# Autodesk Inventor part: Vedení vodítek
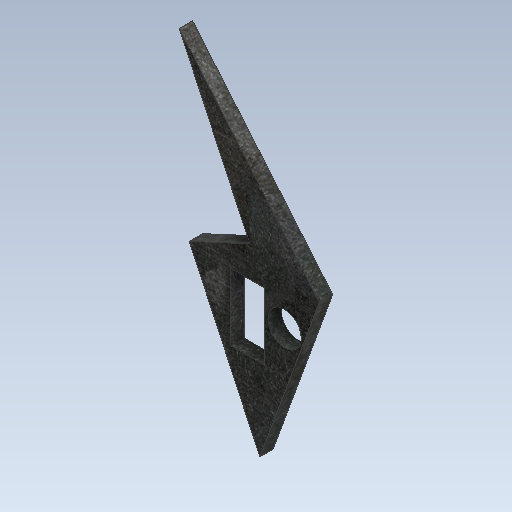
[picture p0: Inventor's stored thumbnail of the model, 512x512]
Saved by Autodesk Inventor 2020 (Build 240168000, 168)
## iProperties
Created: 2025-03
Part Number: Vedení vodítek
Material: Ocel
Document SubType Name: Modeling
Designer: doma
Density: 7.85 g/cm^3
Appearance: Plech
Mass: 300.864 g
Surface Area: 148.491 cm^2
Volume: 38.3267 cm^3
Author: doma
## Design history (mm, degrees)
sketch "Náčrt1"
  geometry: L1 (2141.663, -169.537)-(2099.366, -78.832); L2 (2127.103, -43.665)-(2093.357, 28.704); L3 (2124.351, -80.469)-(2144.351, -80.469); L4 (2127.103, -43.665)-(2134.351, -59.208); L5 (2134.351, -59.208)-(2135.619, -61.927); L6 (2135.619, -61.927)-(2099.366, -78.832); L7 (2144.351, -120.569)-(2124.351, -120.569); L8 (2144.351, -120.569)-(2144.451, -120.569); L9 (2144.351, -80.469)-(2144.451, -80.469); L10 (2144.451, -80.469)-(2144.451, -120.569); L11 (2141.663, -169.537)-(2177.373, -71.423); L12 (2124.351, -120.569)-(2124.351, -80.469); L13 (2093.357, 28.704)-(2177.373, -71.423); 13 further points
  constraints: 26 end point
extrude "Vysunutí1" new body sketch "Náčrt1" distance "d54" = 8; taper "d55" = 0 deg
sketch "Náčrt2"
  geometry: L1 (-2144.451, -80.469)-(-2144.451, -120.569) reference; L2 (-2144.451, -80.469)-(-2144.451, -120.569) reference; L3 (-2141.663, -169.537)-(-2177.373, -71.423) reference; L4 (-2141.663, -169.537)-(-2177.373, -71.423) reference; L5 (-2168.585, -95.569)-(-2144.451, -95.569); L6 (-2144.451, -80.469)-(-2144.451, -120.569) reference; L7 (-2144.451, -120.569)-(-2124.351, -120.569) reference; C1 r 10 at (-2156.518, -95.569); 2 further points
  constraints: 2 end point, 2 point on line, 1 centre point, 1 coincident, 1 midpoint, 1 perpendicular
  dimensions: "d56" = 20 diameter of C1; "d57" = 25 distance between parallel lines of L7 L5
extrude "Vysunutí2" cut sketch "Náčrt2" extent not by distance; stored distance "d58" = 0; taper "d59" = 0 deg
node "Těleso1"
node "Promítnutá smyčka1"
node "Promítnutá smyčka2"
